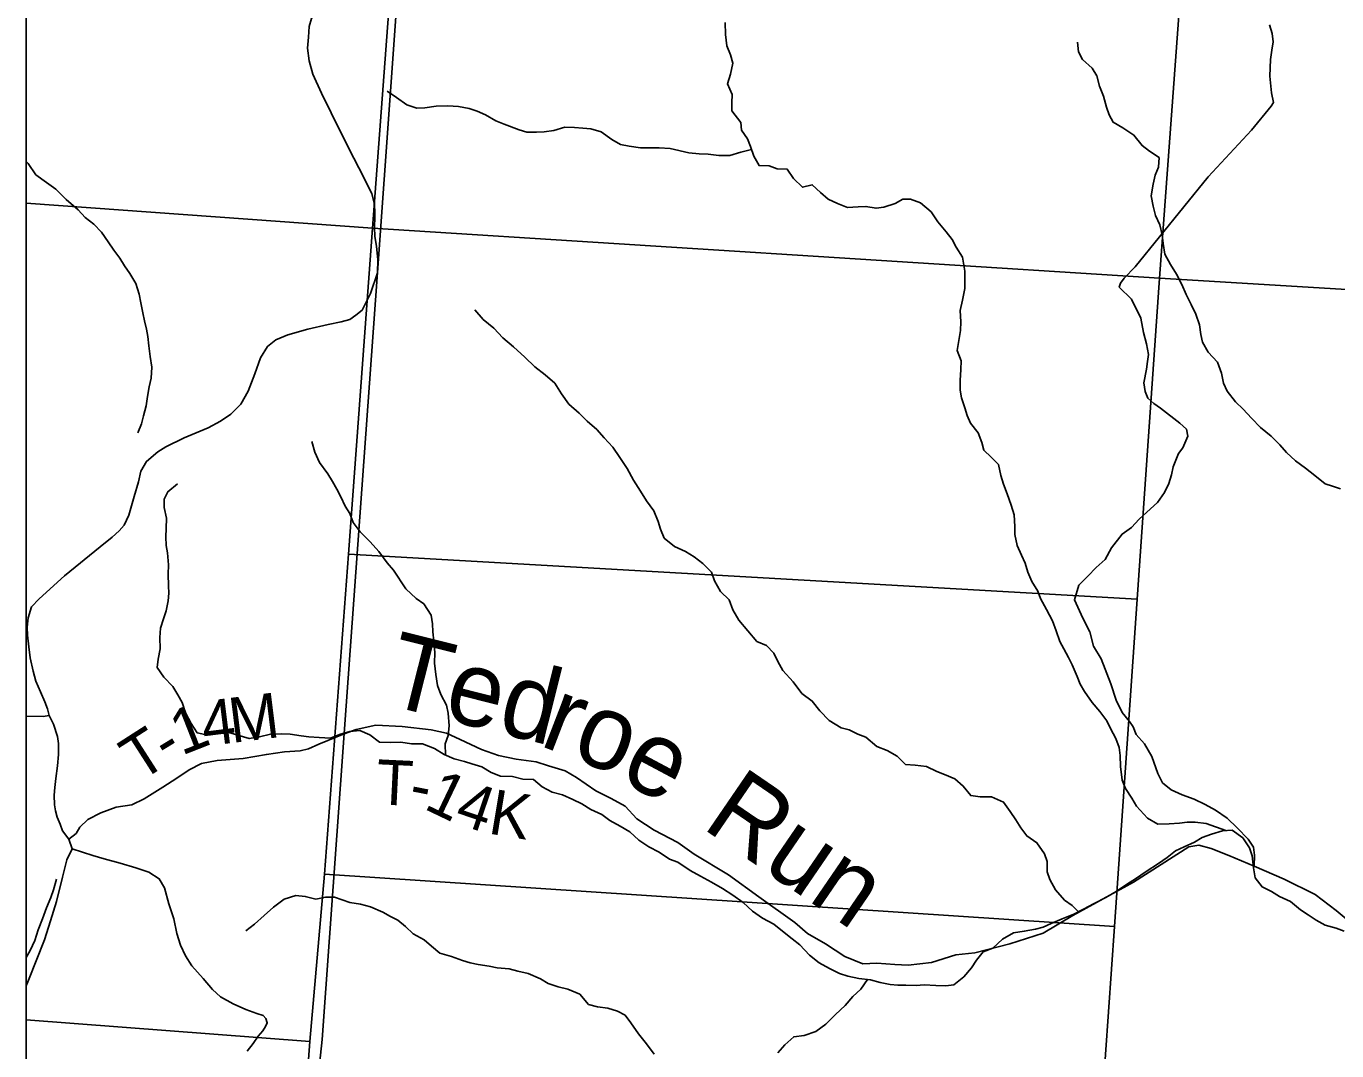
# Model space of a CAD drawing. Extents: x -8.2 to 34, y 0 to 22.
# Drawn here: x 2.1 to 3.755, y 18.871 to 20.164 of the extents above; entities that cross this region are included whole.
import ezdxf

# ---------------------------------------------------------------- set-up
doc = ezdxf.new("R2010")
doc.units = 0
for name, color, linetype in [('GM_X_Corporation', 7, 'Continuous'), ('GM_X_County_Road', 7, 'Continuous'), ('GM_X_Minor_River', 7, 'Continuous'), ('GM_X_Minor_River_Text', 7, 'Continuous'), ('GM_X_Township_Road', 7, 'Continuous'), ('GM_X_Township_Road_Text', 7, 'Continuous'), ('GM_X_Township_Text', 7, 'Continuous'), ('SH_Data', 7, 'Continuous')]:
    doc.layers.add(name, color=color, linetype=linetype)

msp = doc.modelspace()

# ---------------------------------------------------------------- linework, layer by layer
at = {"layer": 'GM_X_Corporation'}
msp.add_lwpolyline([(6.4774, 18.0203), (6.488, 18.1752), (6.5242, 18.7061), (6.5297, 18.7882), (6.5448, 18.981), (6.5455, 18.9878), (6.5461, 19.0017), (6.5463, 19.009), (6.5469, 19.0218), (6.548, 19.0467), (6.5487, 19.0617), (6.5495, 19.0821), (6.5503, 19.0966), (6.5514, 19.1092), (6.5523, 19.118), (6.5529, 19.1264), (6.5537, 19.1382), (6.5541, 19.1447), (6.5536, 19.1514), (6.5814, 19.5334), (6.6608, 20.6695), (6.6768, 20.9), (2.1, 20.9), (2.1, 14.1)], dxfattribs=at)
for points in [[(2.6112, 20.9), (2.1, 20.9), (2.1, 19.9409), (2.5373, 19.9092)], [(3.2326, 20.9), (2.6112, 20.9), (2.5373, 19.9092), (3.5308, 19.8461), (3.6063, 20.8752)], [(4.607, 20.8038), (4.5379, 19.7849), (3.5308, 19.8461), (3.6063, 20.8752)], [(2.1, 19.9409), (2.1, 18.9097), (2.4582, 18.8825), (2.4767, 19.0935), (2.5067, 19.4977), (2.5373, 19.9092)], [(3.5308, 19.8461), (3.5026, 19.4408), (2.5067, 19.4977), (2.5373, 19.9092)], [(3.5308, 19.8461), (4.5379, 19.7849), (4.465, 18.749), (3.459, 18.8121), (3.474, 19.0276), (3.5026, 19.4408)], [(3.5026, 19.4408), (3.474, 19.0276), (2.4767, 19.0935), (2.5067, 19.4977)], [(2.4767, 19.0935), (3.474, 19.0276), (3.459, 18.8121), (3.4438, 18.6343), (2.9025, 18.6602), (2.4436, 18.691), (2.4444, 18.7015), (2.4582, 18.8825)]]:
    msp.add_lwpolyline(points, close=True, dxfattribs=at)
at = {"layer": 'GM_X_County_Road'}
for points in [[(2.54, 19.9286), (2.5395, 19.9394), (2.5363, 19.9525), (2.5262, 19.9731), (2.5074, 20.0097), (2.4852, 20.0546), (2.4727, 20.0797), (2.4618, 20.1034), (2.4574, 20.1204), (2.4552, 20.1365), (2.4562, 20.1505), (2.4574, 20.1639), (2.4601, 20.1737), (2.4653, 20.1828), (2.4721, 20.1885), (2.4819, 20.1935), (2.4937, 20.1976), (2.5078, 20.2011), (2.5287, 20.2021), (2.5491, 20.2008)], [(2.524, 19.8058), (2.5346, 19.8266), (2.5437, 19.8529), (2.5439, 19.8692), (2.5422, 19.8863), (2.5402, 19.8986), (2.5397, 19.9101), (2.5402, 19.9237), (2.54, 19.9286)], [(2.158, 19.1255), (2.1536, 19.1379), (2.1457, 19.1483), (2.1428, 19.1569), (2.139, 19.1657), (2.1368, 19.1737), (2.1359, 19.1813), (2.1352, 19.1933), (2.1362, 19.2031), (2.1374, 19.2145), (2.1397, 19.2303), (2.1409, 19.2446), (2.1409, 19.2585), (2.1397, 19.2674), (2.1346, 19.2829), (2.129, 19.2938), (2.127, 19.3025), (2.1237, 19.3111), (2.1181, 19.3239), (2.1122, 19.3375), (2.1087, 19.35), (2.1052, 19.3669), (2.1035, 19.3805), (2.1017, 19.3953), (2.1012, 19.4056), (2.1025, 19.4175), (2.1068, 19.4313), (2.1165, 19.4412), (2.1484, 19.4704), (2.1932, 19.5068), (2.2087, 19.519), (2.2173, 19.527), (2.2237, 19.5341), (2.2296, 19.5469), (2.2362, 19.5706), (2.2416, 19.5891), (2.2447, 19.6023), (2.2517, 19.6148), (2.2661, 19.6268), (2.2764, 19.6332), (2.2996, 19.6445), (2.3296, 19.657), (2.3451, 19.6655), (2.3585, 19.6743), (2.371, 19.6871), (2.3801, 19.7035), (2.3887, 19.7252), (2.3959, 19.7453), (2.4045, 19.7599), (2.415, 19.7684), (2.4301, 19.7747), (2.4554, 19.7815), (2.4813, 19.7875), (2.4976, 19.7908), (2.5085, 19.7941), (2.5163, 19.7992), (2.524, 19.8058)], [(2.1, 18.9526), (2.103, 18.96), (2.1229, 19.0107), (2.1306, 19.035), (2.1384, 19.0594), (2.146, 19.0901), (2.1511, 19.1116), (2.158, 19.1255)], [(2.158, 19.1255), (2.1843, 19.1173), (2.1985, 19.1132), (2.2185, 19.1075), (2.2384, 19.1015), (2.2546, 19.0961), (2.2679, 19.0879), (2.2745, 19.0765), (2.2802, 19.0562), (2.2862, 19.0375), (2.2903, 19.0189), (2.2948, 19.004), (2.3011, 18.9907), (2.309, 18.978), (2.3236, 18.9622), (2.3353, 18.948), (2.3451, 18.9388), (2.3612, 18.9302), (2.3771, 18.9227), (2.391, 18.9178), (2.399, 18.9152), (2.4026, 18.9113), (2.4044, 18.9062), (2.4023, 18.9013), (2.3987, 18.8958), (2.3928, 18.8891), (2.3864, 18.8801), (2.3791, 18.8703)]]:
    msp.add_lwpolyline(points, dxfattribs=at)
at = {"layer": 'GM_X_Minor_River'}
for points in [[(2.9922, 20.1174), (2.9891, 20.1281), (2.9846, 20.1394), (2.983, 20.1535), (2.9826, 20.1687)], [(3.4845, 20.0358), (3.4724, 20.043), (3.4671, 20.0524), (3.4637, 20.0619), (3.4599, 20.076), (3.4549, 20.0885), (3.4515, 20.1014), (3.4458, 20.1112), (3.4337, 20.1222), (3.4284, 20.1317), (3.4272, 20.1438)], [(3.6145, 19.1488), (3.5897, 19.1577), (3.5757, 19.1592), (3.5658, 19.1592), (3.556, 19.158), (3.5431, 19.1572), (3.5287, 19.1569), (3.5154, 19.1644), (3.5018, 19.1796), (3.4957, 19.1898), (3.4878, 19.202), (3.4836, 19.2122), (3.4817, 19.2297), (3.4809, 19.2437), (3.4797, 19.2536), (3.4756, 19.2649), (3.4691, 19.2775), (3.4642, 19.2873), (3.4555, 19.2991), (3.4456, 19.3104), (3.4361, 19.3241), (3.4308, 19.3336), (3.427, 19.3434), (3.4206, 19.3579), (3.416, 19.3673), (3.4099, 19.378), (3.405, 19.3874), (3.4001, 19.4007), (3.3955, 19.4136), (3.3883, 19.428), (3.3807, 19.4417), (3.3773, 19.4511), (3.3697, 19.4633), (3.3644, 19.475), (3.361, 19.4864), (3.3564, 19.4963), (3.3511, 19.5088), (3.348, 19.5224), (3.348, 19.5327), (3.3473, 19.5475), (3.3435, 19.5596), (3.3385, 19.574), (3.334, 19.5862), (3.3305, 19.5968), (3.3275, 19.6108), (3.3184, 19.6203), (3.3089, 19.629), (3.3066, 19.6385), (3.3017, 19.651), (3.2922, 19.6632), (3.288, 19.6726), (3.285, 19.6825), (3.2808, 19.695), (3.2789, 19.7045), (3.2789, 19.717), (3.28, 19.7307), (3.2804, 19.7417), (3.2754, 19.7546), (3.2773, 19.7675), (3.2796, 19.78), (3.2799, 19.791), (3.2792, 19.8054), (3.2822, 19.8183), (3.2848, 19.8331), (3.2848, 19.8551), (3.2821, 19.8725), (3.2742, 19.8854), (3.2688, 19.8949), (3.2613, 19.9044), (3.251, 19.9173), (3.2423, 19.9298), (3.229, 19.9412), (3.2165, 19.9457), (3.2067, 19.9457), (3.1969, 19.9404), (3.1828, 19.9355), (3.173, 19.9343), (3.1601, 19.9366), (3.1503, 19.9362), (3.137, 19.9354), (3.1241, 19.9404), (3.1124, 19.9457), (3.1029, 19.9544), (3.0923, 19.9639), (3.0802, 19.9608), (3.0685, 19.9718), (3.0609, 19.9836), (3.048, 19.9843), (3.0381, 19.9877), (3.0253, 19.9881), (3.0184, 20.0002), (3.0143, 20.0124), (3.0105, 20.0219), (3.0029, 20.0329), (3.0021, 20.0427), (2.9907, 20.0575), (2.9907, 20.0674), (2.9911, 20.078), (2.9854, 20.0916), (2.9892, 20.1034), (2.9922, 20.1174)], [(3.0156, 20.0084), (3.0021, 20.0052), (2.9885, 20.001), (2.9745, 20.001), (2.9609, 20.0025), (2.9495, 20.0029), (2.9366, 20.0044), (2.9128, 20.0097), (2.8991, 20.0104), (2.8859, 20.0108), (2.8757, 20.0108), (2.8613, 20.0127), (2.8503, 20.015), (2.8393, 20.021), (2.8257, 20.0309), (2.8128, 20.0347), (2.8026, 20.0354), (2.792, 20.0362), (2.7802, 20.0365), (2.7662, 20.0324), (2.7541, 20.0308), (2.7443, 20.0305), (2.7321, 20.0305), (2.7223, 20.0335), (2.7033, 20.0403), (2.6927, 20.0448), (2.6799, 20.0524), (2.6692, 20.057), (2.6594, 20.0604), (2.6458, 20.0627), (2.6325, 20.0638), (2.6177, 20.063), (2.6034, 20.0611), (2.5931, 20.0607), (2.5806, 20.0649), (2.5674, 20.074), (2.5556, 20.082)], [(3.7592, 19.58), (3.7493, 19.5834), (3.7399, 19.5864), (3.727, 19.597), (3.7149, 19.6061), (3.7024, 19.6156), (3.691, 19.6262), (3.6826, 19.6357), (3.6716, 19.6467), (3.6584, 19.6577), (3.647, 19.6694), (3.6364, 19.6808), (3.6269, 19.6899), (3.6163, 19.7035), (3.6114, 19.7134), (3.6091, 19.7263), (3.6041, 19.7399), (3.5924, 19.7528), (3.5852, 19.7654), (3.5829, 19.7748), (3.5814, 19.787), (3.5768, 19.8006), (3.5707, 19.8128), (3.5643, 19.8253), (3.559, 19.8382), (3.5521, 19.8511), (3.5445, 19.8632), (3.5377, 19.8765), (3.5354, 19.8897), (3.5343, 19.9007), (3.5312, 19.9136), (3.5259, 19.925), (3.5229, 19.9368), (3.5202, 19.9501), (3.5228, 19.9648), (3.5251, 19.9762), (3.5293, 19.9861), (3.5304, 19.9982), (3.5183, 20.0062), (3.5088, 20.0134), (3.4985, 20.0267), (3.4845, 20.0358)], [(2.1, 19.9935), (2.1025, 19.9907), (2.112, 19.9767), (2.1256, 19.9668), (2.1373, 19.9585), (2.1506, 19.9452), (2.1654, 19.9323), (2.1745, 19.9228), (2.1855, 19.9141), (2.195, 19.9043), (2.2033, 19.8921), (2.2105, 19.8815), (2.2181, 19.8713), (2.2242, 19.8618), (2.231, 19.8519), (2.2382, 19.8394), (2.2428, 19.8258), (2.2447, 19.8148), (2.2473, 19.8022), (2.2492, 19.7924), (2.2519, 19.7818), (2.2534, 19.7723), (2.2546, 19.7605), (2.2565, 19.7472), (2.2588, 19.7336), (2.2577, 19.7199), (2.2554, 19.7089), (2.2531, 19.6968), (2.2513, 19.685), (2.2479, 19.6721), (2.2456, 19.6623), (2.2411, 19.6509)], [(3.4284, 19.0463), (3.4205, 19.054), (3.411, 19.0608), (3.3993, 19.0741), (3.3925, 19.087), (3.389, 19.0965), (3.389, 19.1097), (3.3856, 19.1192), (3.3761, 19.1333), (3.3632, 19.142), (3.3557, 19.1522), (3.3492, 19.1621), (3.3424, 19.1727), (3.334, 19.1844), (3.3185, 19.1913), (3.3045, 19.1913), (3.2924, 19.1928), (3.2829, 19.2049), (3.2723, 19.214), (3.2594, 19.2197), (3.2496, 19.2235), (3.2367, 19.2295), (3.2223, 19.2314), (3.2102, 19.2322), (3.1995, 19.2428), (3.187, 19.25), (3.1738, 19.2549), (3.1601, 19.2667), (3.1499, 19.2705), (3.1389, 19.2761), (3.1287, 19.2784), (3.1139, 19.2875), (3.1018, 19.3), (3.0923, 19.3122), (3.0794, 19.3216), (3.0684, 19.3364), (3.0552, 19.3508), (3.0487, 19.3622), (3.0438, 19.3725), (3.0347, 19.3823), (3.0225, 19.3876), (3.0112, 19.4009), (2.9998, 19.4145), (2.9922, 19.4274), (2.9873, 19.4399), (2.9767, 19.4506), (2.9691, 19.4638), (2.9653, 19.4748), (2.9543, 19.4858), (2.9433, 19.4942), (2.9323, 19.501), (2.9183, 19.5074), (2.9054, 19.518), (2.9008, 19.5294), (2.8978, 19.5389), (2.8925, 19.5522), (2.883, 19.5651), (2.8754, 19.5772), (2.8667, 19.5912), (2.8587, 19.6057), (2.8496, 19.6197), (2.8405, 19.6326), (2.8295, 19.6447), (2.8204, 19.6549), (2.8083, 19.6656), (2.7981, 19.6758), (2.7852, 19.6872), (2.7757, 19.7001), (2.7673, 19.7137), (2.7552, 19.724), (2.7423, 19.7342), (2.7294, 19.7463), (2.7154, 19.7596), (2.7018, 19.7706), (2.6904, 19.7831), (2.6771, 19.7937), (2.6665, 19.8059)], [(2.6293, 19.2441), (2.6289, 19.2581), (2.6327, 19.2687), (2.6338, 19.2808), (2.6326, 19.2968), (2.6304, 19.307), (2.6235, 19.3203), (2.6193, 19.3317), (2.6171, 19.3457), (2.6155, 19.3601), (2.6159, 19.3734), (2.6147, 19.3878), (2.6132, 19.3996), (2.6128, 19.4098), (2.6113, 19.4208), (2.6022, 19.4348), (2.5923, 19.4417), (2.5791, 19.4538), (2.5639, 19.4773), (2.5559, 19.4868), (2.5453, 19.5012), (2.5343, 19.5133), (2.5218, 19.5258), (2.5127, 19.5376), (2.5085, 19.549), (2.5028, 19.5584), (2.4971, 19.5702), (2.4922, 19.5797), (2.4865, 19.5892), (2.4808, 19.599), (2.4702, 19.6134), (2.4645, 19.6263), (2.4607, 19.64)], [(3.2336, 18.9541), (3.2234, 18.953), (3.2105, 18.9537), (3.2006, 18.9534), (3.1908, 18.9545), (3.1783, 18.9571), (3.1658, 18.9602), (3.151, 18.9621), (3.1374, 18.9651), (3.1268, 18.9685), (3.1143, 18.9746), (3.101, 18.9818), (3.0889, 18.9916), (3.0768, 19.0045), (3.0669, 19.0121), (3.057, 19.0201), (3.0438, 19.0307), (3.0294, 19.0382), (3.0169, 19.047), (3.0051, 19.058), (2.9919, 19.0674), (2.979, 19.0758), (2.965, 19.0837), (2.9513, 19.0913), (2.9384, 19.0985), (2.9225, 19.1088), (2.9123, 19.1125), (2.899, 19.1216), (2.8861, 19.1281), (2.8733, 19.1368), (2.8619, 19.147), (2.8498, 19.1542), (2.8369, 19.1614), (2.8267, 19.169), (2.813, 19.1755), (2.8013, 19.1823), (2.7903, 19.188), (2.777, 19.1937), (2.7638, 19.1971), (2.7513, 19.2039), (2.7406, 19.2134), (2.727, 19.2137), (2.7138, 19.2168), (2.6986, 19.2175), (2.6872, 19.2221), (2.6751, 19.2293), (2.6626, 19.233), (2.6532, 19.2361), (2.6403, 19.2395), (2.6278, 19.2448), (2.6153, 19.2524), (2.6001, 19.2584), (2.5865, 19.2584), (2.5728, 19.2603), (2.56, 19.2599), (2.546, 19.2603), (2.5338, 19.2694), (2.5213, 19.2751), (2.5085, 19.2736), (2.4956, 19.2701), (2.4842, 19.2652), (2.4698, 19.2663), (2.457, 19.2671), (2.4471, 19.2682), (2.4331, 19.2705), (2.4218, 19.2709), (2.4085, 19.2705), (2.3945, 19.2671), (2.3816, 19.2648), (2.3559, 19.2724), (2.3422, 19.2708), (2.3294, 19.2693), (2.3157, 19.2723), (2.3081, 19.2837), (2.3013, 19.2974), (2.2967, 19.3103), (2.2914, 19.3201), (2.285, 19.3307), (2.2736, 19.3425), (2.2653, 19.3546), (2.2664, 19.3653), (2.269, 19.3781), (2.2686, 19.3926), (2.2694, 19.4043), (2.2735, 19.4161), (2.2765, 19.4263), (2.2792, 19.4388), (2.2799, 19.4483), (2.2795, 19.4578), (2.2791, 19.4726), (2.2795, 19.4844), (2.2784, 19.4992), (2.2768, 19.5086), (2.2764, 19.5196), (2.2768, 19.5299), (2.2772, 19.5432), (2.2741, 19.5564), (2.2741, 19.5671), (2.279, 19.5765), (2.2911, 19.5864)], [(3.764, 19.0219), (3.7538, 19.0257), (3.7401, 19.0295), (3.7284, 19.0356), (3.7185, 19.0424), (3.7087, 19.0488), (3.6962, 19.0591), (3.6822, 19.0655), (3.6723, 19.072), (3.6602, 19.0777), (3.6515, 19.089), (3.6496, 19.1015), (3.6476, 19.1167), (3.6442, 19.127), (3.6359, 19.1395), (3.6226, 19.1493), (3.6101, 19.1486), (3.5965, 19.1444), (3.5848, 19.1398), (3.5749, 19.1341), (3.5621, 19.1281), (3.5511, 19.1231), (3.5405, 19.1148), (3.5295, 19.1072), (3.514, 19.0969), (3.5004, 19.0878), (3.4905, 19.0817), (3.4762, 19.0719), (3.4629, 19.0643), (3.4482, 19.0567), (3.4349, 19.0495), (3.4224, 19.0434), (3.4077, 19.0373), (3.394, 19.0316), (3.3838, 19.0267), (3.374, 19.0244), (3.36, 19.0217), (3.3463, 19.0198), (3.3327, 19.0115), (3.3202, 19.0001), (3.3081, 18.9955), (3.2998, 18.9853), (3.2934, 18.9754), (3.2836, 18.964), (3.2711, 18.9538), (3.2612, 18.9526), (3.2483, 18.953), (3.2336, 18.9541)], [(2.1, 18.9884), (2.1048, 18.9972), (2.1108, 19.0101), (2.1153, 19.0234), (2.1206, 19.0374), (2.1255, 19.0511), (2.1312, 19.0644), (2.1346, 19.0739), (2.1383, 19.0875)], [(2.8929, 18.8663), (2.883, 18.8796), (2.8728, 18.8921), (2.8633, 18.9062), (2.8561, 18.9156), (2.8463, 18.9206), (2.8341, 18.9247), (2.8213, 18.9262), (2.8099, 18.9293), (2.7989, 18.9422), (2.7837, 18.9486), (2.7716, 18.9513), (2.7591, 18.9558), (2.7493, 18.9615), (2.7337, 18.9683), (2.7205, 18.9713), (2.7099, 18.974), (2.6947, 18.9755), (2.6845, 18.9774), (2.6705, 18.9797), (2.6606, 18.9819), (2.6508, 18.9846), (2.6368, 18.9899), (2.6224, 18.994), (2.6118, 19.0028), (2.6023, 19.0107), (2.5886, 19.0183), (2.5788, 19.0278), (2.5693, 19.0357), (2.5598, 19.0403), (2.5504, 19.0456), (2.5345, 19.0524), (2.522, 19.0558), (2.5087, 19.0581), (2.4989, 19.0615), (2.4894, 19.0645), (2.478, 19.0645), (2.4655, 19.0623), (2.4523, 19.0657), (2.4405, 19.0668), (2.4258, 19.0622), (2.4122, 19.052), (2.4004, 19.0417), (2.3883, 19.0307), (2.3774, 19.022)], [(3.1622, 18.9606), (3.1537, 18.9484), (3.1435, 18.9393), (3.134, 18.9279), (3.1219, 18.9165), (3.1094, 18.9044), (3.097, 18.8953), (3.0822, 18.89), (3.0689, 18.8884), (3.0576, 18.8782), (3.0489, 18.8683)]]:
    msp.add_lwpolyline(points, dxfattribs=at)
at = {"layer": 'GM_X_Township_Road'}
for points in [[(3.6469, 20.033), (3.6719, 20.063), (3.6748, 20.0679), (3.6723, 20.0799), (3.67, 20.1012), (3.6707, 20.1221), (3.6726, 20.1339), (3.6742, 20.1443), (3.6732, 20.1548), (3.6697, 20.1659)], [(3.6502, 19.104), (3.6509, 19.1176), (3.6493, 19.1278), (3.6426, 19.1379), (3.6289, 19.1524), (3.6162, 19.1642), (3.6013, 19.1743), (3.5883, 19.1816), (3.5747, 19.1883), (3.5594, 19.1937), (3.5455, 19.2), (3.5347, 19.2092), (3.5287, 19.2206), (3.521, 19.2422), (3.5118, 19.2584), (3.5014, 19.2702), (3.4975, 19.2797), (3.4928, 19.2863), (3.4836, 19.2978), (3.476, 19.3133), (3.4693, 19.3339), (3.4572, 19.3654), (3.4474, 19.3816), (3.4426, 19.3996), (3.4341, 19.4168), (3.4233, 19.4399), (3.429, 19.4587), (3.4404, 19.4701), (3.4506, 19.4807), (3.4623, 19.491), (3.4703, 19.5056), (3.4836, 19.5231), (3.4952, 19.5315), (3.505, 19.5418), (3.5147, 19.5506), (3.5283, 19.5628), (3.5372, 19.5753), (3.5425, 19.5867), (3.5459, 19.598), (3.5479, 19.608), (3.5548, 19.6248), (3.5602, 19.6321), (3.5666, 19.6467), (3.565, 19.6554), (3.5564, 19.6632), (3.5321, 19.6819), (3.5234, 19.6878), (3.5161, 19.6948), (3.5128, 19.7032), (3.5109, 19.714), (3.5145, 19.7311), (3.5156, 19.7407), (3.5169, 19.7497), (3.5145, 19.7632), (3.5104, 19.7776), (3.5074, 19.7957), (3.4952, 19.8197), (3.4799, 19.8346), (3.4815, 19.8397), (3.4863, 19.846), (3.5002, 19.8603), (3.5923, 19.9739), (3.6469, 20.033)], [(2.1, 19.2932), (2.1216, 19.2926), (2.129, 19.2938)], [(2.5016, 19.2708), (2.5167, 19.2765), (2.5414, 19.2816), (2.5746, 19.2803), (2.6113, 19.2759), (2.6306, 19.2715), (2.648, 19.2639), (2.6746, 19.2509), (2.6962, 19.2433), (2.7186, 19.2389), (2.7436, 19.2354), (2.7595, 19.2303), (2.7804, 19.2243), (2.7949, 19.2158), (2.8193, 19.199), (2.8386, 19.1892), (2.856, 19.1797), (2.8709, 19.1635), (2.8927, 19.1493), (2.9225, 19.1335), (2.9434, 19.1189), (2.9867, 19.0929), (3.025, 19.0651), (3.0703, 19.0325), (3.0865, 19.0189), (3.1092, 19.0059), (3.1333, 18.9897), (3.1561, 18.9806), (3.1738, 18.9812), (3.1966, 18.9796), (3.2134, 18.979), (3.2428, 18.9821), (3.2735, 18.992), (3.2976, 18.9945), (3.3419, 19.0059), (3.384, 19.0192), (3.4214, 19.0417), (3.498, 19.0838), (3.5676, 19.1281), (3.5803, 19.1303), (3.5958, 19.1262), (3.6183, 19.1173), (3.6502, 19.104), (3.6882, 19.0872), (3.7271, 19.0679), (3.7537, 19.048), (3.7886, 19.0189)], [(2.1536, 19.1379), (2.1629, 19.1452), (2.1678, 19.1531), (2.1776, 19.1629), (2.1944, 19.1711), (2.2137, 19.1781), (2.2334, 19.1813), (2.2489, 19.1889), (2.2723, 19.2034), (2.29, 19.2151), (2.3058, 19.2256), (2.3214, 19.2335), (2.341, 19.237), (2.3739, 19.2398), (2.4033, 19.2449), (2.4261, 19.248), (2.4458, 19.2493), (2.4562, 19.2518), (2.4695, 19.2579), (2.5016, 19.2708)]]:
    msp.add_lwpolyline(points, dxfattribs=at)
at = {"layer": 'GM_X_Township_Text'}
msp.add_lwpolyline([(2.227, 15.7788), (2.2908, 16.5825), (2.3045, 16.7554), (2.3047, 16.7573), (2.3109, 16.8355), (2.3177, 16.9219), (2.3436, 17.248), (2.3535, 17.3723), (2.3875, 17.8009), (2.3895, 17.8266), (2.4044, 18.0138), (2.4049, 18.02), (2.4177, 18.1814), (2.4336, 18.4736), (2.4376, 18.5459), (2.4377, 18.5489), (2.4735, 18.885), (2.5013, 19.2713), (2.5435, 19.8534), (2.5683, 20.2001), (2.5873, 20.4639), (2.6187, 20.9)], dxfattribs=at)
at = {"layer": 'SH_Data'}
msp.add_line((2.1, 20.9), (2.1, 14.1), dxfattribs=at)

# ---------------------------------------------------------------- texts
at = {"layer": 'GM_X_Minor_River_Text'}
for s, rotation, p in [('Ted', 345.9081, (2.5491, 19.3091)), ('ro', 338.9077, (2.7461, 19.2568)), ('e', 331.9073, (2.846, 19.2139)), ('Run', 325.6197, (2.9513, 19.1531))]:
    msp.add_text(s, height=0.0947, rotation=rotation, dxfattribs=at).set_placement(p)
at = {"layer": 'GM_X_Township_Road_Text'}
for s, rotation, p in [('4', 7.1036, (2.3248, 19.2549)), ('M', 7.0488, (2.3592, 19.2592)), ('1', 21.4391, (2.2961, 19.2431)), ('T', 32.6602, (2.2433, 19.2095)), ('-', 31.4629, (2.2787, 19.2322)), ('T', 357.2433, (2.5409, 19.182)), ('1', 334.4311, (2.6005, 19.177)), ('-', 349.0667, (2.5813, 19.1802)), ('4', 341.1633, (2.6389, 19.1591)), ('K', 350.5923, (2.6819, 19.1453))]:
    msp.add_text(s, height=0.0568, rotation=rotation, dxfattribs=at).set_placement(p)

doc.saveas('drawing.dxf')
